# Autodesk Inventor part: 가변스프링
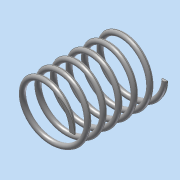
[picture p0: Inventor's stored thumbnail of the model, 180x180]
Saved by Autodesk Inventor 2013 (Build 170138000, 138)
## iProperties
Created: 2018-06
Part Number: 가변스프링
Material: 강철, 연강
Document SubType Name: Modeling
Designer: Administrator
Density: 7.86 g/cm^3
Mass: 83.1343 g
Surface Area: 106.475 cm^2
Volume: 10.5769 cm^3
Author: Administrator
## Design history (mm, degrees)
sketch "스케치1"
  geometry: L1 (0, 0)-(22.5, 0); L2 (0, 0)-(0, 73.25); L3 (0, 73.25)-(22.5, 73.25); C1 r 2 at (22.5, 0)
  constraints: 6 end point, 2 perpendicular, 1 centre point, 1 coincident, 1 horizontal
  dimensions: "d0" = 22.5 distance of L1.start L1.end; "d1" = 4 diameter of C1; "d2" = 73.25 distance of L1.start L2.end (derived); "d3" = 22.5 distance of L2.end L3.end
feature "코일1" sketch "스케치1" pitch "d4" = 10; turns "d6" = 6; dims "d5" = 73.25 (= d2), "d7" = 0, angle "d8" = 90 deg, angle "d9" = 90 deg, "d10" = 0, "d11" = 0
sketch "스케치2"
  geometry: L1 (0, -25)-(73.25, -25); L2 (73.25, -25)-(73.25, 25); L3 (73.25, 25)-(0, 25); L4 (0, 25)-(0, -25); 2 further points
  constraints: 8 end point, 2 parallel, 1 coincident, 1 horizontal, 1 midpoint, 1 perpendicular
  dimensions: "d12" = 73.25 distance of L2.end L3.end (derived); "d14" = 50 distance of L1.end L2.end
extrude "돌출1" sketch "스케치2" stored distance "d15" = 0; taper "d16" = 0 deg
node "솔리드1"
